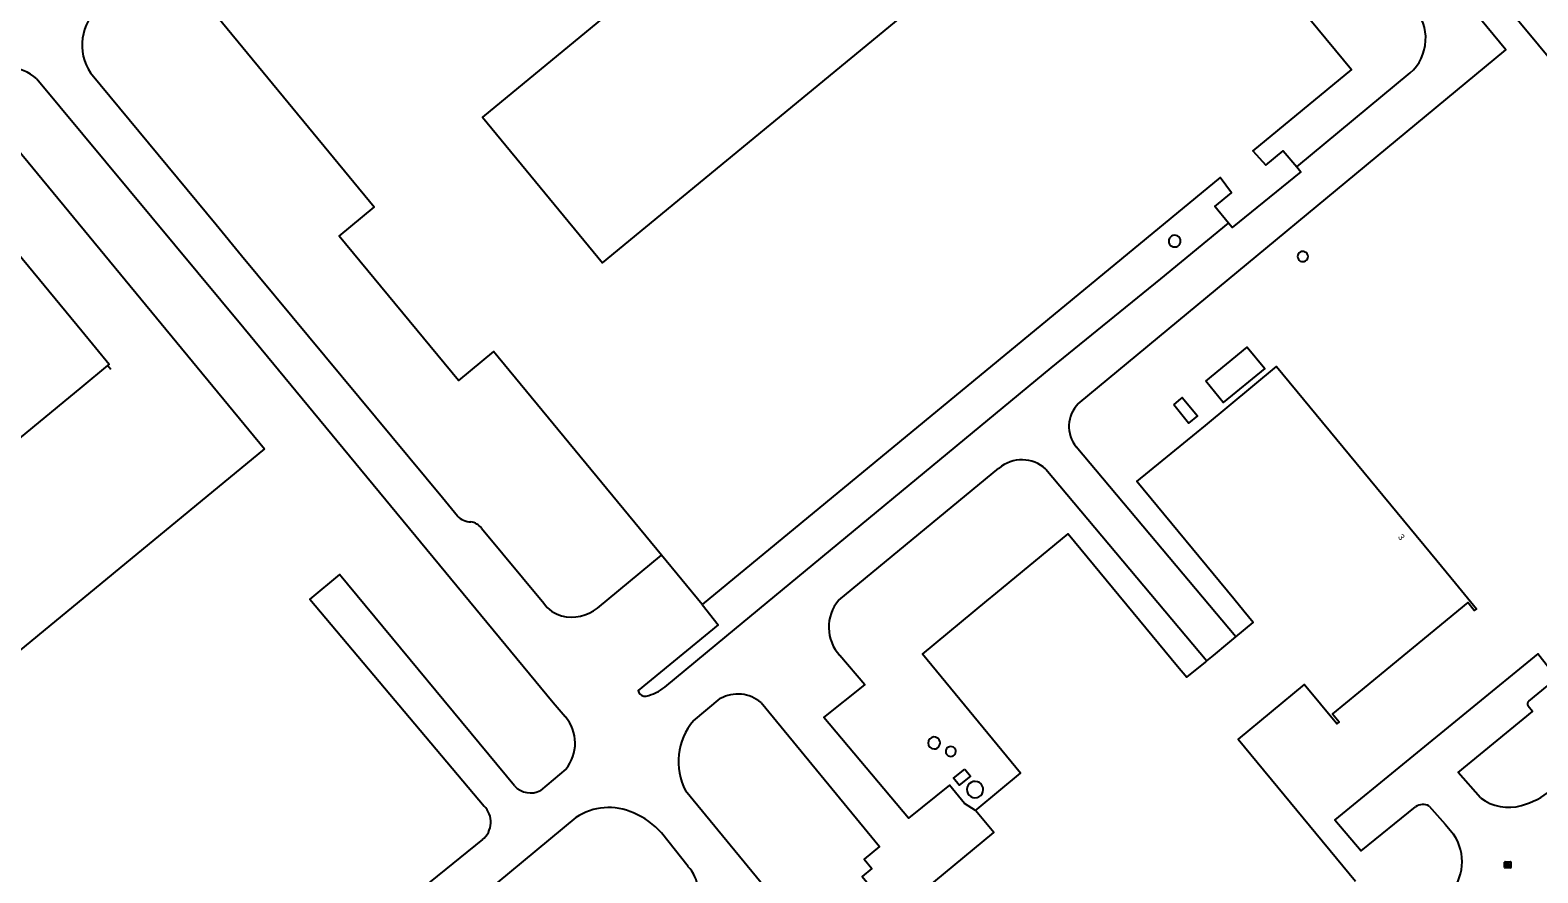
# Model space of a CAD drawing. Extents: x 156141 to 158132, y 385651 to 388399.
# Drawn here: x 156991.7 to 157235, y 386785.7 to 386921.8 of the extents above; entities that cross this region are included whole.
import ezdxf

# ---------------------------------------------------------------- set-up
doc = ezdxf.new("R2010")
doc.units = 0
for name, color, linetype in [('IMGEO_Berm_groen', 7, 'Continuous'), ('IMGEO_Hek', 7, 'Continuous'), ('IMGEO_Opslagtank', 7, 'Continuous'), ('IMGEO_Pand', 7, 'Continuous'), ('IMGEO_Pand_nummerreeks', 7, 'Continuous'), ('IMGEO_Rijbaan_lokaal_open', 7, 'Continuous'), ('IMGEO_Rioolput', 7, 'Continuous')]:
    doc.layers.add(name, color=color, linetype=linetype)

msp = doc.modelspace()

# ---------------------------------------------------------------- linework, layer by layer
at = {"layer": 'IMGEO_Berm_groen'}
msp.add_lwpolyline([(157241.17, 386912.07), (157168.24, 387000), (157137.21, 387037.65), (157129.35, 387046.65), (157129.18, 387046.53), (157127.01, 387049.14), (157127.14, 387049.25), (157124.86, 387052.05), (157124.73, 387051.94), (157091.86, 387091.79), (157084.85, 387100.37), (157072.38, 387115.63), (157065.43, 387124.28), (157056.49, 387135.39)], dxfattribs=at)
at = {"layer": 'IMGEO_Hek'}
for points in [[(156981.2, 386912.78), (157029.48, 386854.2)], [(157004.69, 386867.04), (157004.18, 386867.66)], [(157029.48, 386854.2), (156858.45, 386713.3)]]:
    msp.add_lwpolyline(points, dxfattribs=at)
at = {"layer": 'IMGEO_Opslagtank'}
msp.add_lwpolyline([(157142.52, 386802.5), (157143.46, 386801.37), (157141.6, 386799.89), (157140.69, 386801.04), (157142.52, 386802.5)], dxfattribs=at)
for centre, radius, start, end in [((157176.37, 386887.76), 0.942, 89.9808, 273.1829), ((157176.41, 386887.76), 0.942, 270.6494, 92.5143), ((157197.05, 386885.27), 0.823, 89.6447, 272.7931), ((157197.09, 386885.27), 0.823, 270.0595, 92.3782), ((157137.57, 386806.71), 0.963, 91.4765, 270.1298), ((157137.57, 386806.71), 0.963, 269.8855, 91.7208), ((157140.23, 386805.33), 0.797, 86.6683, 270.6689), ((157140.28, 386805.33), 0.796, 267.4073, 89.9299), ((157144.16, 386799.17), 1.32, 87.5499, 269.369), ((157144.18, 386799.17), 1.32, 268.4143, 88.5046)]:
    msp.add_arc(centre, radius, start, end, dxfattribs=at)
at = {"layer": 'IMGEO_Pand'}
for points in [[(157110.85, 387029.54), (157151.92, 386979.73), (157064.67, 386907.78), (157084.05, 386884.24), (157171.32, 386956.18), (157204.92, 386915.47), (157189.01, 386902.35), (157191.11, 386900.04), (157193.9, 386902.32), (157196.1, 386899.73)], [(157093.59, 386837.01), (157066.45, 386869.91), (157060.78, 386865.23), (157041.56, 386888.57), (157047.21, 386893.24), (157016.15, 386930.98)], [(156975.66, 386902.77), (157000, 386873.24), (157004.43, 386867.87), (157004.18, 386867.66), (157000, 386864.22), (156951.3, 386824.08)], [(157196.1, 386899.73), (157196.78, 386898.93), (157185.65, 386889.95), (157185.09, 386890.64)], [(157185.09, 386890.64), (157182.9, 386893.32), (157185.57, 386895.57), (157183.76, 386898.02), (157100.14, 386829.08)], [(157181.4, 386865.13), (157188.11, 386870.64), (157190.94, 386867.2), (157184.23, 386861.69), (157181.4, 386865.13)], [(157186.24, 386823.83), (157189.06, 386826.16), (157187.56, 386827.97), (157185.93, 386829.96), (157170.31, 386848.91), (157179.92, 386856.81), (157181.39, 386857.98), (157192.85, 386867.51), (157218.69, 386836.2), (157221.74, 386832.51), (157225.13, 386828.39), (157224.75, 386828.09), (157223.73, 386829.37), (157206.06, 386814.86), (157201.85, 386811.41), (157202.94, 386810.1), (157202.64, 386809.85), (157202.57, 386809.79), (157197.3, 386816.16), (157186.62, 386807.33), (157205.58, 386784.37)], [(157176.23, 386861.34), (157177.43, 386862.34), (157177.6, 386862.48), (157180.07, 386859.53), (157178.64, 386858.38), (157176.23, 386861.34)], [(157144.25, 386795.82), (157144.5, 386796.03), (157151.51, 386801.84), (157135.67, 386821.07), (157146.07, 386829.64), (157147.53, 386830.85), (157159.21, 386840.48), (157176.87, 386819.12), (157178.37, 386817.31), (157181.35, 386819.78), (157181.57, 386819.96)], [(157100.14, 386829.08), (157093.59, 386837.01)], [(157181.57, 386819.96), (157182.65, 386820.85), (157184.95, 386822.76), (157186.24, 386823.83)], [(157134.38, 386781.62), (157147.22, 386792.23), (157144.25, 386795.82)]]:
    msp.add_lwpolyline(points, dxfattribs=at)
at = {"layer": 'IMGEO_Rijbaan_lokaal_open'}
for points in [[(157160.83, 386861.48), (157229.85, 386918.64), (157081.95, 387097.87), (157078.51, 387102.05)], [(156992.74, 386913.98), (157026.17, 386873.74), (157042.17, 386854.32), (157076.11, 386813.25), (157078.01, 386810.98)], [(157001.44, 386914.91), (157021.68, 386890.42), (157025.76, 386885.45), (157058.21, 386846.34), (157060.62, 386843.41)], [(157196.1, 386899.73), (157214.42, 386914.91)], [(157094.13, 386815.73), (157104.12, 386824), (157156.44, 386867.28), (157174.17, 386881.65), (157185.09, 386890.64)], [(157186.24, 386823.83), (157160.5, 386854.53)], [(157122.17, 386829.78), (157148.03, 386851.06)], [(157155.6, 386850.94), (157181.57, 386819.96)], [(157064.52, 386841.41), (157074.56, 386829.29)], [(157083.22, 386828.47), (157093.59, 386837.01)], [(157069.86, 386799.79), (157041.62, 386833.93), (157036.83, 386829.91), (157064.93, 386796.51)], [(157100.14, 386829.08), (157102.7, 386825.8), (157089.78, 386815.17), (157089.9, 386814.87)], [(157233.56, 386813.45), (157238.06, 386817.15), (157234.98, 386821.09), (157202.26, 386794.31), (157206.51, 386789.27), (157215.25, 386796.38)], [(157144.25, 386795.82), (157142.48, 386796.94), (157140.04, 386799.87), (157133.44, 386794.55), (157119.75, 386810.82), (157126.38, 386816.12), (157122.35, 386820.82)], [(157098.74, 386810.28), (157103.06, 386813.88)], [(157109.65, 386813.22), (157128.74, 386789.98), (157126.28, 386787.92), (157127.5, 386786.45), (157125.94, 386785.15), (157127.23, 386783.6), (157121.86, 386779.19), (157114.12, 386778.66), (157097.46, 386799)], [(157225.76, 386797.84), (157222.14, 386801.96), (157234.12, 386811.8), (157233.43, 386812.64)], [(157078.13, 386802.48), (157074.03, 386799.05)], [(157079.74, 386794.67), (157060.52, 386778.76), (157059.95, 386778.28), (157047.58, 386767.81), (157036.03, 386758.64), (157025.63, 386747.93), (156986.8, 386708.06), (156987.93, 386706.73), (156922.25, 386652.43), (156921.77, 386652.52)], [(157217.49, 386796.51), (157220.05, 386793.61), (157221.37, 386791.98)], [(157097.85, 386786.78), (157093.59, 386792.18)], [(157064.67, 386791.09), (157056.24, 386784.27), (157032.01, 386764.67), (157032.83, 386763.49), (157023.49, 386753.81), (157013.9, 386743.93), (157001.36, 386731.03), (156988.46, 386717.66), (156981.68, 386711.24)]]:
    msp.add_lwpolyline(points, dxfattribs=at)
for centre, radius, start, end in [((157007.99, 386919.4), 7.94, 129.1008, 214.4206), ((157209.47, 386920.47), 7.44, 311.7538, 42.3613), ((156987.7, 386908.28), 7.6, 48.4891, 121.992), ((157164.56, 386857.83), 5.23, 135.616, 219.0144), ((157151.75, 386846.7), 5.73, 47.7391, 130.4607), ((157062.73, 386845.21), 2.78, 220.3423, 271.7037), ((157062.14, 386839.38), 3.13, 40.3504, 77.505), ((157078.83, 386832.28), 5.22, 214.9869, 254.7007), ((157079.1, 386833.65), 6.62, 255.5709, 308.4707), ((157127.34, 386825.4), 6.77, 139.6901, 222.5848), ((157090.89, 386815.34), 1.1, 205.4277, 280.9463), ((157089.02, 386822.39), 8.39, 284.347, 307.473), ((157105.88, 386808.77), 5.83, 49.684, 118.9568), ((157233.93, 386812.98), 0.599, 127.5817, 214.3862), ((157073.06, 386806.66), 6.57, 320.5156, 41.0767), ((157106.32, 386803.7), 10.03, 139.0309, 207.9776), ((157072.41, 386802.02), 3.39, 221.2465, 298.6639), ((157229.03, 386808.78), 12.62, 285.3281, 309.8566), ((157216.47, 386794.73), 2.05, 60.184, 126.405), ((157230.3, 386803.88), 7.56, 233.0705, 285.8807), ((157062.38, 386793.92), 3.64, 309.0219, 45.3957), ((157085.06, 386786.67), 9.61, 65.4413, 123.6381), ((157084.11, 386783.68), 12.73, 41.8466, 67.1091), ((157215.08, 386787.53), 7.71, 314.6968, 35.2826), ((157094.01, 386782.99), 5.39, 319.7619, 44.7219)]:
    msp.add_arc(centre, radius, start, end, dxfattribs=at)
at = {"layer": 'IMGEO_Rioolput'}
for p, q in [((157229.64, 386786.59), (157229.64, 386787.44)), ((157229.72, 386787.52), (157230.57, 386787.52)), ((157230.13, 386787.3), (157230.16, 386787.3)), ((157230.64, 386787.44), (157230.64, 386786.59)), ((157230.57, 386786.52), (157229.72, 386786.52)), ((157230.15, 386786.74), (157230.13, 386786.74))]:
    msp.add_line(p, q, dxfattribs=at)
for points in [[(157229.64, 386786.59), (157229.64, 386787.44)], [(157229.72, 386787.52), (157230.57, 386787.52)], [(157230.23, 386787.21), (157229.98, 386787.22), (157229.98, 386786.82)], [(157229.98, 386786.82), (157230.1, 386786.82), (157230.1, 386786.98), (157230.12, 386786.98)], [(157230.16, 386787.14), (157230.1, 386787.14), (157230.1, 386787.05)], [(157230.1, 386787.05), (157230.16, 386787.05)], [(157230.16, 386786.95), (157230.23, 386786.82), (157230.37, 386786.82), (157230.31, 386786.94)], [(157230.64, 386787.44), (157230.64, 386786.59)], [(157230.57, 386786.52), (157229.72, 386786.52)]]:
    msp.add_lwpolyline(points, dxfattribs=at)
for centre, radius, start, end in [((157229.72, 386787.44), 0.0765, 91.552, 178.448), ((157229.72, 386787.44), 0.0765, 91.552, 178.448), ((157230.11, 386786.93), 0.0533, 26.0293, 88.6989), ((157230.16, 386787.04), 0.0964, 77.0061, 93.1865), ((157230.14, 386787.24), 0.19, 274.7715, 282.9687), ((157230.18, 386787.1), 0.0378, 276.6634, 79.6772), ((157230.23, 386787.11), 0.109, 350.3612, 89.416), ((157230.23, 386787.1), 0.112, 277.5842, 350.9817), ((157230.21, 386786.89), 0.108, 29.5134, 73.7905), ((157230.57, 386787.44), 0.0765, 1.552, 88.448), ((157230.57, 386787.44), 0.0765, 1.552, 88.448), ((157229.72, 386786.59), 0.0765, 181.552, 268.448), ((157229.72, 386786.59), 0.0765, 181.552, 268.448), ((157230.57, 386786.59), 0.0765, 271.552, 358.448), ((157230.57, 386786.59), 0.0765, 271.552, 358.448)]:
    msp.add_arc(centre, radius, start, end, dxfattribs=at)
for centre, major_axis, ratio, start_param, end_param in [((157230.13, 386787.02), (-0.387, 0.002), 0.722429, 4.712389, 7.853982), ((157230.15, 386787.02), (-0.39, 0.002), 0.717154, 1.570796, 4.712389)]:
    msp.add_ellipse(centre, major_axis=major_axis, ratio=ratio, start_param=start_param, end_param=end_param, dxfattribs=at)

# ---------------------------------------------------------------- texts
at = {"layer": 'IMGEO_Pand_nummerreeks'}
msp.add_text('3', height=1, rotation=309.5339, dxfattribs=at).set_placement((157212.37, 386839.93))

doc.saveas('drawing.dxf')
